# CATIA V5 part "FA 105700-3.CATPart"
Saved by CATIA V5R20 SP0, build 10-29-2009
Part number: FA 105700-3
Revision: ANY
Definition: UNKNOWN
Nomenclature: FA 105700-3
Source: Unknown
Bounding box of the stored display mesh (mm): x -2.687 to 2.687, y -2.475 to 2.475, z -2.5 to 2.5
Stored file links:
  C:\Users\Utente\Desktop\IO LAVORO\3D X SITO CF\CUMSA\3D files FA\FA 1057SF\FA 105700-3.CATPart

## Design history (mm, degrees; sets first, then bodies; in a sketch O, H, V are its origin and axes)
Body1 "Chaflán4" (main body)
  Solid1: solid without history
